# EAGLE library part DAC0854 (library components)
Quad 8-bit DAC. Controlled by SPI.
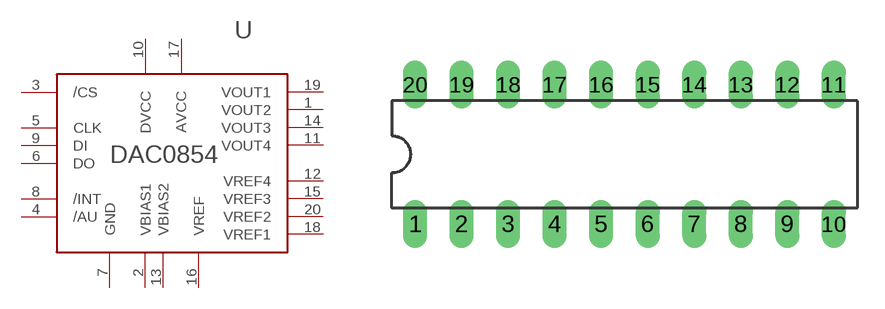
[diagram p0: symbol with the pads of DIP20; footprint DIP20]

Designator prefix -

## DAC0854  [DIP20]
1  VOUT2  out
2  VBIAS1  in
3  /CS  in
4  /AU  in
5  CLK  in
6  DO  out
7  GND  pas
8  /INT  out
9  DI  in
10  DVCC  pwr
11  VOUT4  out
12  VREF4  in
13  VBIAS2  in
14  VOUT3  out
15  VREF3  in
16  VREF  out
17  AVCC  pwr
18  VREF1  in
19  VOUT1  out
20  VREF2  in

## Footprint DIP20 (pad centres in mm)
DIP20
drill 0.813 long: 1 -11.43,-3.81; 2 -8.89,-3.81; 3 -6.35,-3.81; 4 -3.81,-3.81; 5 -1.27,-3.81; 6 1.27,-3.81; 7 3.81,-3.81; 8 6.35,-3.81; 9 8.89,-3.81; 10 11.43,-3.81; 11 11.43,3.81; 12 8.89,3.81; 13 6.35,3.81; 14 3.81,3.81; 15 1.27,3.81; 16 -1.27,3.81; 17 -3.81,3.81; 18 -6.35,3.81; 19 -8.89,3.81; 20 -11.43,3.81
